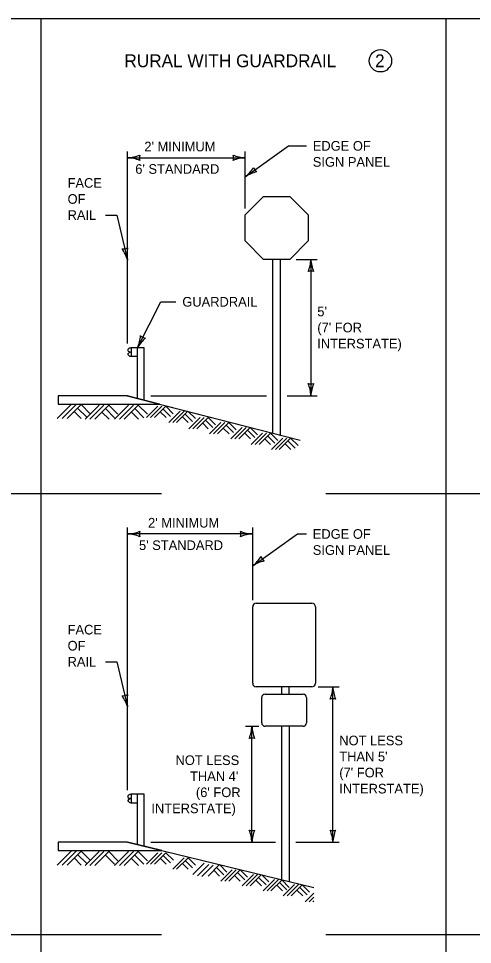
# Model space of a CAD drawing. Extents: x 49991.4 to 50021, y 49987.6 to 50011.4.
# Drawn here: x 50003.09 to 50005.92, y 49993.23 to 49999 of the extents above; entities that cross this region are included whole.
import ezdxf

# ---------------------------------------------------------------- set-up
doc = ezdxf.new("R2010")
doc.units = 0
for name, color, linetype in [('Level 1', 7, 'Continuous'), ('Level 2', 7, 'Continuous'), ('Level 3', 7, 'Continuous')]:
    doc.layers.add(name, color=color, linetype=linetype)

msp = doc.modelspace()

# ---------------------------------------------------------------- linework, layer by layer
at = {"layer": 'Level 1'}
for p, q in [((50004.6721, 49996.4167), (50004.6721, 49997.4987)), ((50004.7207, 49996.4043), (50004.7207, 49997.4987)), ((50003.8291, 49996.948), (50003.7885, 49996.948)), ((50003.7903, 49996.948), (50003.7903, 49996.8947)), ((50003.8291, 49996.6327), (50003.8291, 49996.948)), ((50003.872, 49996.948), (50003.8291, 49996.948)), ((50003.872, 49996.6219), (50003.872, 49996.948)), ((50003.7885, 49996.8947), (50003.8291, 49996.8947)), ((50003.768, 49996.649), (50003.336, 49996.649)), ((50003.336, 49996.649), (50003.336, 49996.5973)), ((50003.7649, 49996.649), (50003.336, 49996.649)), ((50003.336, 49996.649), (50003.336, 49996.5973)), ((50003.7649, 49996.649), (50004.8425, 49996.3731)), ((50003.9668, 49996.5973), (50003.7649, 49996.649)), ((50003.3298, 49996.5067), (50003.4171, 49996.5941)), ((50003.336, 49996.5973), (50003.9668, 49996.5973)), ((50003.336, 49996.5973), (50003.9668, 49996.5973)), ((50003.3605, 49996.5067), (50003.4478, 49996.5941)), ((50003.3909, 49996.5067), (50003.4782, 49996.5941)), ((50003.4351, 49996.5508), (50003.4792, 49996.5067)), ((50003.4568, 49996.5725), (50003.5135, 49996.5158)), ((50003.4782, 49996.5941), (50003.5351, 49996.5373)), ((50003.5026, 49996.5031), (50003.5899, 49996.5904)), ((50003.5333, 49996.5031), (50003.6206, 49996.5904)), ((50003.5637, 49996.5031), (50003.6511, 49996.5904)), ((50003.6079, 49996.5471), (50003.652, 49996.5031)), ((50003.6295, 49996.5688), (50003.6862, 49996.5122)), ((50003.6511, 49996.5904), (50003.7079, 49996.5337)), ((50003.6861, 49996.5031), (50003.7734, 49996.5904)), ((50003.7168, 49996.5031), (50003.8041, 49996.5904)), ((50003.7472, 49996.5031), (50003.8346, 49996.5904)), ((50003.7914, 49996.5471), (50003.8355, 49996.5031)), ((50003.813, 49996.5688), (50003.8697, 49996.5122)), ((50003.8346, 49996.5904), (50003.8914, 49996.5337)), ((50003.8863, 49996.5126), (50003.957, 49996.5833)), ((50003.9112, 49996.5126), (50003.9819, 49996.5833)), ((50003.9358, 49996.5126), (50004.0065, 49996.5833)), ((50003.9665, 49996.5973), (50003.9665, 49996.5973)), ((50003.9665, 49996.5973), (50003.9665, 49996.5973)), ((50003.9668, 49996.5973), (50004.8425, 49996.3731)), ((50003.9716, 49996.5483), (50004.0075, 49996.5126)), ((50003.9891, 49996.5659), (50004.0352, 49996.52)), ((50004.0065, 49996.5833), (50004.0526, 49996.5373)), ((50004.0238, 49996.4819), (50004.0945, 49996.5526)), ((50004.0486, 49996.4819), (50004.1193, 49996.5526)), ((50004.0732, 49996.4819), (50004.1435, 49996.552)), ((50004.145, 49996.5517), (50004.19, 49996.5066)), ((50004.109, 49996.5175), (50004.1449, 49996.4819)), ((50004.1266, 49996.5352), (50004.1726, 49996.4893)), ((50004.1495, 49996.4436), (50004.2202, 49996.5143)), ((50004.1744, 49996.4436), (50004.2451, 49996.5143)), ((50004.199, 49996.4436), (50004.2697, 49996.5143)), ((50004.2524, 49996.4969), (50004.2983, 49996.451)), ((50004.2697, 49996.5143), (50004.3158, 49996.4683)), ((50004.2348, 49996.4793), (50004.2706, 49996.4436)), ((50004.2786, 49996.4118), (50004.3493, 49996.4826)), ((50004.3035, 49996.4118), (50004.3743, 49996.4826)), ((50004.3282, 49996.4118), (50004.3989, 49996.4826)), ((50004.3639, 49996.4474), (50004.3997, 49996.4118)), ((50004.3814, 49996.4651), (50004.4274, 49996.4192)), ((50004.3989, 49996.4826), (50004.445, 49996.4365)), ((50004.4114, 49996.3813), (50004.4821, 49996.452)), ((50004.4362, 49996.3813), (50004.5071, 49996.452)), ((50004.461, 49996.3813), (50004.5317, 49996.452)), ((50004.5142, 49996.4346), (50004.5602, 49996.3889)), ((50004.5317, 49996.452), (50004.5778, 49996.4062)), ((50004.4967, 49996.417), (50004.5324, 49996.3813)), ((50004.5369, 49996.3456), (50004.6076, 49996.4164)), ((50004.5619, 49996.3456), (50004.6326, 49996.4164)), ((50004.5864, 49996.3456), (50004.6571, 49996.4164)), ((50004.6221, 49996.3813), (50004.6579, 49996.3456)), ((50004.6396, 49996.3989), (50004.6857, 49996.353)), ((50004.6571, 49996.4164), (50004.7033, 49996.3703)), ((50004.6631, 49996.3145), (50004.7338, 49996.3852)), ((50004.688, 49996.3145), (50004.7588, 49996.3852)), ((50004.7126, 49996.3145), (50004.7834, 49996.3852)), ((50004.7834, 49996.3852), (50004.8295, 49996.3393)), ((50004.7485, 49996.3502), (50004.7842, 49996.3145)), ((50004.766, 49996.3678), (50004.812, 49996.3219)), ((50004.5469, 49994.8576), (50004.5469, 49995.3338)), ((50004.5694, 49995.3563), (50004.9155, 49995.3563)), ((50004.938, 49995.3338), (50004.938, 49994.8576)), ((50004.9155, 49994.8351), (50004.5694, 49994.8351)), ((50004.728, 49994.7902), (50004.728, 49994.8351)), ((50004.7742, 49994.7902), (50004.7742, 49994.8351)), ((50004.603, 49994.611), (50004.603, 49994.7687)), ((50004.6245, 49994.7902), (50004.8605, 49994.7902)), ((50004.882, 49994.7687), (50004.882, 49994.611)), ((50004.8605, 49994.5895), (50004.6245, 49994.5895)), ((50004.728, 49993.6337), (50004.728, 49994.5895)), ((50004.7766, 49993.6218), (50004.7766, 49994.5895)), ((50003.829, 49994.1664), (50003.7884, 49994.1664)), ((50003.7902, 49994.1664), (50003.7902, 49994.1131)), ((50003.829, 49993.8511), (50003.829, 49994.1664)), ((50003.8719, 49994.1664), (50003.829, 49994.1664)), ((50003.8719, 49993.8403), (50003.8719, 49994.1664)), ((50003.7884, 49994.1131), (50003.829, 49994.1131)), ((50003.768, 49993.8673), (50003.336, 49993.8673)), ((50003.336, 49993.8673), (50003.336, 49993.8156)), ((50003.768, 49993.8673), (50003.336, 49993.8673)), ((50003.336, 49993.8673), (50003.336, 49993.8156)), ((50003.768, 49993.8673), (50004.9267, 49993.5853)), ((50003.9804, 49993.8156), (50003.768, 49993.8673)), ((50003.3299, 49993.725), (50003.4172, 49993.8124)), ((50003.336, 49993.8156), (50003.9804, 49993.8156)), ((50003.336, 49993.8156), (50003.9804, 49993.8156)), ((50003.3605, 49993.725), (50003.4479, 49993.8124)), ((50003.391, 49993.725), (50003.4783, 49993.8124)), ((50003.4568, 49993.7908), (50003.5136, 49993.7341)), ((50003.4783, 49993.8124), (50003.5352, 49993.7556)), ((50003.5027, 49993.7214), (50003.59, 49993.8087)), ((50003.5334, 49993.7214), (50003.6207, 49993.8087)), ((50003.5638, 49993.7214), (50003.6511, 49993.8087)), ((50003.6295, 49993.7871), (50003.6863, 49993.7305)), ((50003.6511, 49993.8087), (50003.708, 49993.752)), ((50003.6862, 49993.7214), (50003.7735, 49993.8087)), ((50003.7169, 49993.7214), (50003.8042, 49993.8087)), ((50003.7473, 49993.7214), (50003.8346, 49993.8087)), ((50003.813, 49993.7871), (50003.8698, 49993.7305)), ((50003.8346, 49993.8087), (50003.8915, 49993.752)), ((50003.8864, 49993.7309), (50003.9571, 49993.8016)), ((50003.9113, 49993.7309), (50003.982, 49993.8016)), ((50003.9359, 49993.7309), (50004.0066, 49993.8016)), ((50003.9666, 49993.8156), (50003.9666, 49993.8156)), ((50003.9891, 49993.7842), (50004.0352, 49993.7383)), ((50004.0066, 49993.8016), (50004.0527, 49993.7556)), ((50003.4351, 49993.7691), (50003.4793, 49993.725)), ((50003.7915, 49993.7654), (50003.8356, 49993.7214)), ((50003.9717, 49993.7666), (50004.0076, 49993.7309)), ((50004.0487, 49993.7002), (50004.1194, 49993.7709)), ((50004.0733, 49993.7002), (50004.1441, 49993.7709)), ((50004.1091, 49993.7358), (50004.145, 49993.7002)), ((50004.1267, 49993.7535), (50004.1726, 49993.7076)), ((50004.1441, 49993.7709), (50004.1901, 49993.7249)), ((50004.1739, 49993.6666), (50004.2446, 49993.7373)), ((50004.2027, 49993.6589), (50004.2734, 49993.7296)), ((50004.2296, 49993.6532), (50004.3003, 49993.7239)), ((50004.2689, 49993.6569), (50004.3396, 49993.7277)), ((50004.3396, 49993.7277), (50004.3857, 49993.6817)), ((50004.3047, 49993.6927), (50004.3404, 49993.6569)), ((50004.3222, 49993.7103), (50004.3682, 49993.6643)), ((50004.3484, 49993.6252), (50004.4191, 49993.696)), ((50004.3734, 49993.6252), (50004.4441, 49993.696)), ((50004.398, 49993.6252), (50004.4687, 49993.696)), ((50004.4338, 49993.6608), (50004.4696, 49993.6252)), ((50004.4513, 49993.6785), (50004.4972, 49993.6326)), ((50004.4687, 49993.696), (50004.5148, 49993.6499)), ((50004.4812, 49993.5947), (50004.5519, 49993.6654)), ((50004.5061, 49993.5947), (50004.5769, 49993.6654)), ((50004.5308, 49993.5947), (50004.6007, 49993.6646)), ((50004.6028, 49993.6641), (50004.6476, 49993.6196)), ((50004.5666, 49993.6304), (50004.6023, 49993.5947)), ((50004.5841, 49993.648), (50004.63, 49993.6023)), ((50004.6112, 49993.5639), (50004.6819, 49993.6347)), ((50004.6361, 49993.5639), (50004.7069, 49993.6347)), ((50004.6606, 49993.5639), (50004.7287, 49993.632)), ((50004.7139, 49993.6172), (50004.76, 49993.5713)), ((50004.7287, 49993.6321), (50004.7749, 49993.586)), ((50004.7374, 49993.5328), (50004.8081, 49993.6035)), ((50004.7623, 49993.5328), (50004.8331, 49993.6035)), ((50004.7869, 49993.5328), (50004.8555, 49993.6013)), ((50004.8555, 49993.6013), (50004.9016, 49993.5553)), ((50004.6964, 49993.5996), (50004.7322, 49993.5639)), ((50004.8228, 49993.5685), (50004.8585, 49993.5328)), ((50004.8403, 49993.586), (50004.8862, 49993.5402)), ((50004.8728, 49993.4969), (50004.9267, 49993.5508)), ((50004.8977, 49993.4969), (50004.9267, 49993.5259)), ((50004.9222, 49993.4969), (50004.9267, 49993.5014))]:
    msp.add_line(p, q, dxfattribs=at)
for points in [[(49999.3835, 49998.9992), (50016.7501, 49998.9992), (50016.7501, 49987.7988), (49999.3835, 49987.7988)], [(50004.615, 49997.8908), (50004.7778, 49997.8908), (50004.8925, 49997.7761), (50004.8925, 49997.6134), (50004.7778, 49997.4987), (50004.615, 49997.4987), (50004.5004, 49997.6134), (50004.5004, 49997.7761)]]:
    msp.add_lwpolyline(points, close=True, dxfattribs=at)
for centre, radius, start, end in [((50004.5694, 49995.3338), 0.0225, 90, 180), ((50004.9155, 49995.3338), 0.0225, 0, 90), ((50004.5694, 49994.8576), 0.0225, 180, 270), ((50004.9155, 49994.8576), 0.0225, 270, 0), ((50004.6245, 49994.7687), 0.0215, 90, 180), ((50004.8605, 49994.7687), 0.0215, 0, 90), ((50004.6245, 49994.611), 0.0215, 180, 270), ((50004.8605, 49994.611), 0.0215, 270, 0)]:
    msp.add_arc(centre, radius, start, end, dxfattribs=at)
for points in [[(50003.7885, 49996.948), (50003.7698, 49996.9374), (50003.7694, 49996.9304), (50003.7885, 49996.9213), (50003.7892, 49996.9211), (50003.7694, 49996.9099), (50003.7698, 49996.9062), (50003.7885, 49996.8947)], [(50003.7884, 49994.1664), (50003.7697, 49994.1558), (50003.7693, 49994.1488), (50003.7884, 49994.1397), (50003.7891, 49994.1395), (50003.7693, 49994.1283), (50003.7697, 49994.1246), (50003.7884, 49994.1131)]]:
    msp.add_spline(points, degree=3, dxfattribs=at)
at = {"layer": 'Level 2'}
msp.add_line((50004.5004, 49997.8908), (50004.5004, 49997.8908), dxfattribs=at)
msp.add_circle((50005.3426, 49998.7359), 0.0693, dxfattribs=at)
at = {"layer": 'Level 3'}
for p, q in [((50003.2287, 49987.7988), (50003.2287, 49998.9992)), ((50005.7525, 49987.7988), (50005.7525, 49998.9992)), ((50003.768, 49996.9736), (50003.768, 49998.1717)), ((50004.5004, 49998.0135), (50004.7704, 49998.2058)), ((50004.5004, 49997.8161), (50004.5004, 49998.1717)), ((50004.7704, 49998.2058), (50004.8812, 49998.2058)), ((50003.768, 49998.1317), (50004.5004, 49998.1317)), ((50003.6292, 49997.7749), (50003.7012, 49997.7749)), ((50003.7012, 49997.7749), (50003.768, 49997.4934)), ((50004.8178, 49997.4987), (50004.9493, 49997.4987)), ((50004.9093, 49997.4987), (50004.9093, 49996.649)), ((50003.8291, 49996.948), (50003.9743, 49997.2343)), ((50003.9743, 49997.2343), (50004.0685, 49997.2343)), ((50003.912, 49996.649), (50004.6321, 49996.649)), ((50004.7607, 49996.649), (50004.9493, 49996.649)), ((50002.4787, 49996.0407), (50003.9787, 49996.0407)), ((50005.0025, 49996.0407), (50006.5025, 49996.0407)), ((50003.768, 49994.1922), (50003.768, 49995.8278)), ((50004.5469, 49995.3751), (50004.5469, 49995.8278)), ((50004.5469, 49995.7878), (50003.768, 49995.7878)), ((50004.5469, 49995.5893), (50004.8257, 49995.7878)), ((50004.8257, 49995.7878), (50004.8811, 49995.7878)), ((50003.6292, 49994.9917), (50003.7012, 49994.9917)), ((50003.7012, 49994.9917), (50003.768, 49994.7102)), ((50004.9555, 49994.8351), (50005.0862, 49994.8351)), ((50005.0462, 49993.8673), (50005.0462, 49994.8351)), ((50004.502, 49994.5895), (50004.5845, 49994.5895)), ((50004.542, 49993.8673), (50004.542, 49994.5895)), ((50003.9119, 49993.8673), (50004.688, 49993.8673)), ((50004.8166, 49993.8673), (50005.0862, 49993.8673)), ((50002.4787, 49993.2934), (50003.9787, 49993.2934)), ((50005.0025, 49993.2934), (50006.5025, 49993.2934))]:
    msp.add_line(p, q, dxfattribs=at)
for centre, radius, start, end in [((50003.7565, 49998.3644), 0.233, 272.82731, 292.07716), ((50003.7588, 49997.9096), 0.2223, 67.45601, 87.63952), ((50003.8962, 49998.1317), 0.0548, 162.13882, 197.86118), ((50004.5096, 49998.3538), 0.2223, 247.45601, 267.63952), ((50004.3722, 49998.1317), 0.0548, 342.13882, 17.86118), ((50004.5119, 49997.899), 0.233, 92.82731, 112.07716), ((50004.356, 49998.1964), 0.233, 308.28663, 327.53647), ((50004.6218, 49997.8273), 0.2223, 102.91533, 123.09883), ((50004.6048, 49998.0879), 0.0548, 197.59813, 233.32049), ((50003.7376, 49997.618), 0.0548, 265.84975, 301.57211), ((50003.5446, 49997.4271), 0.233, 16.53824, 35.78809), ((50003.986, 49997.5372), 0.2223, 171.16694, 191.35045), ((50004.6872, 49997.5079), 0.2223, 337.45601, 357.63952), ((50005.142, 49997.5102), 0.233, 182.82731, 202.07716), ((50004.9093, 49997.3705), 0.0548, 72.13882, 107.86118), ((50003.617, 49997.0445), 0.233, 335.53959, 354.78944), ((50004.0223, 49996.838), 0.2223, 130.16829, 150.3518), ((50003.8878, 49997.0619), 0.0548, 224.8511, 260.57346), ((50004.9093, 49996.7772), 0.0548, 252.13882, 287.86118), ((50004.6766, 49996.6375), 0.233, 2.82731, 22.07716), ((50005.1314, 49996.6398), 0.2223, 157.45601, 177.63952), ((50003.7565, 49996.0205), 0.233, 272.82731, 292.07716), ((50003.8962, 49995.7878), 0.0548, 162.13882, 197.86118), ((50004.5561, 49996.0099), 0.2223, 247.45601, 267.63952), ((50004.4187, 49995.7878), 0.0548, 342.13882, 17.86118), ((50003.7588, 49995.5657), 0.2223, 67.45601, 87.63952), ((50004.5584, 49995.5551), 0.233, 92.82731, 112.07716), ((50004.4026, 49995.7722), 0.233, 308.27741, 327.52726), ((50004.6513, 49995.6637), 0.0548, 197.58892, 233.31128), ((50004.6683, 49995.403), 0.2223, 102.90611, 123.08962), ((50004.8241, 49994.8443), 0.2223, 337.45601, 357.63952), ((50005.2789, 49994.8466), 0.233, 182.82731, 202.07716), ((50003.7376, 49994.8348), 0.0548, 265.84975, 301.57211), ((50003.5446, 49994.6439), 0.233, 16.53824, 35.78809), ((50003.986, 49994.754), 0.2223, 171.16694, 191.35045), ((50005.0462, 49994.7069), 0.0548, 72.13882, 107.86118), ((50004.3199, 49994.5987), 0.2223, 337.45601, 357.63952), ((50004.7747, 49994.601), 0.233, 182.82731, 202.07716), ((50004.542, 49994.4613), 0.0548, 72.13882, 107.86118), ((50004.542, 49993.9955), 0.0548, 252.13882, 287.86118), ((50004.3093, 49993.8558), 0.233, 2.82731, 22.07716), ((50004.7641, 49993.8581), 0.2223, 157.45601, 177.63952), ((50005.0462, 49993.9955), 0.0548, 252.13882, 287.86118), ((50004.8135, 49993.8558), 0.233, 2.82731, 22.07716), ((50005.2683, 49993.8581), 0.2223, 157.45601, 177.63952)]:
    msp.add_arc(centre, radius, start, end, dxfattribs=at)

# ---------------------------------------------------------------- texts
at = {"layer": 'Level 2'}
for s, height, p in [('RURAL WITH GUARDRAIL', 0.08, (50003.748, 49998.6959)), ('2', 0.08, (50005.3091, 49998.6959)), ("2' MINIMUM", 0.06, (50003.872, 49998.1717)), ('EDGE OF', 0.06, (50004.9212, 49998.1758)), ('SIGN PANEL', 0.06, (50004.9212, 49998.0758)), ("6' STANDARD", 0.06, (50003.8156, 49998.0317)), ('FACE', 0.06, (50003.3941, 49997.9449)), ('OF', 0.06, (50003.3941, 49997.8449)), ('RAIL', 0.06, (50003.3941, 49997.7449)), ('GUARDRAIL', 0.06, (50004.1085, 49997.2043)), ("5'", 0.06, (50004.9493, 49997.1438)), ("(7' FOR", 0.06, (50004.9493, 49997.0438)), ('INTERSTATE)', 0.06, (50004.9493, 49996.9438)), ("2' MINIMUM", 0.06, (50003.8952, 49995.8278)), ('EDGE OF', 0.06, (50004.9211, 49995.7578)), ("5' STANDARD", 0.06, (50003.8388, 49995.6878)), ('SIGN PANEL', 0.06, (50004.9211, 49995.6578)), ('FACE', 0.06, (50003.3941, 49995.1617)), ('OF', 0.06, (50003.3941, 49995.0617)), ('RAIL', 0.06, (50003.3941, 49994.9617)), ('NOT LESS', 0.06, (50005.0862, 49994.4712)), ('NOT LESS', 0.06, (50004.0663, 49994.3484)), ("THAN 5'", 0.06, (50005.0862, 49994.3712)), ("THAN 4'", 0.06, (50004.1567, 49994.2484)), ("(7' FOR", 0.06, (50005.0862, 49994.2712)), ("(6' FOR", 0.06, (50004.1933, 49994.1484)), ('INTERSTATE)', 0.06, (50005.0862, 49994.1712)), ('INTERSTATE)', 0.06, (50003.9159, 49994.0484))]:
    msp.add_text(s, height=height, dxfattribs=at).set_placement(p)

doc.saveas('drawing.dxf')
